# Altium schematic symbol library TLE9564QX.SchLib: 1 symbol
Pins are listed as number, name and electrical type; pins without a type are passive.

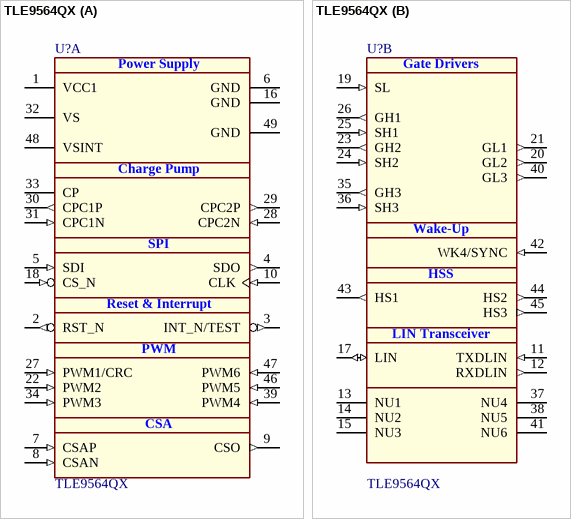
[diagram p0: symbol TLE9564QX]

## TLE9564QX
designator U?
Bridge SBC Family; Manufacturer: Infineon Technologies
part A pins: 1 VCC1 (power) "Voltage Regulator. Output voltage 1", 2 RST_N (out) "Reset Output. Active LOW, internally pull-up", 3 INT_N/TEST (out) "Interrupt Output. Active LOW output TEST", 4 SDO (out) "SPI SBC Data Output to Microcontroller", 5 SDI (in) "SPI SBC Data Input from Microcontroller", 6 GND (power) "Ground. Analog/digital ground", 7 CSAP (in) "Not Inverting input of Current Sense Amplifier", 8 CSAN (in) "Inverting input of Current Sense Amplifier", 9 CSO (out) "Current Sense Amplifier Output", 10 CLK (in) "SPI Clock Input", 16 GND (power) "Ground", 18 CS_N (in) "SPI Chip Select Not input", 22 PWM2 (in) "PWM input 2", 27 PWM1/CRC (in) "PWM input 1", 28 CPC2N (in) "Negative connection to Charge Pump Capacitor 2", 29 CPC2P (out) "Positive connection to Charge Pump Capacitor 2", 30 CPC1P (out) "Positive connection to Charge Pump Capacitor 1", 31 CPC1N (in) "Negative connection to Charge Pump Capacitor 1", 32 VS (power) "Bridge Drivers and Charge pump supply voltage", 33 CP (power) "Charge Pump output voltage", 34 PWM3 (in) "PWM input 3", 39 PWM4 (in) "PWM input 4", 46 PWM5 (in) "PWM input 5", 47 PWM6 (in) "PWM input 6", 48 VSINT (power) "Voltage regulator and SBC supply voltage", 49 GND (power) "Cooling Tab - Exposed Die Pad; Do not use as an electric Ground"
part B pins: 11 TXDLIN (in) "Transmit LIN", 12 RXDLIN (out) "Receive LIN", 13 NU1 "not used", 14 NU2 "not used", 15 NU3 "not used", 17 LIN (io) "LIN Bus", 19 SL (in) "Source Low Side", 20 GL2 (out) "Gate Low Side 2", 21 GL1 (out) "Gate Low Side 1", 23 GH2 (out) "Gate High Side 2", 24 SH2 (in) "Source High Side 2", 25 SH1 (in) "Source High Side 1", 26 GH1 (out) "Gate High Side 1", 35 GH3 (out) "Gate High Side 3", 36 SH3 (in) "Source High Side 3", 37 NU4 "Not used", 38 NU5 "Not used", 40 GL3 (out) "Gate Low Side 3", 41 NU6 "Not used", 42 WK4/SYNC (in) "Wake-up input 4/Sync", 43 HS1 (out) "High Side output 1", 44 HS2 (out) "High Side output 2", 45 HS3 (out) "High Side output 3"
